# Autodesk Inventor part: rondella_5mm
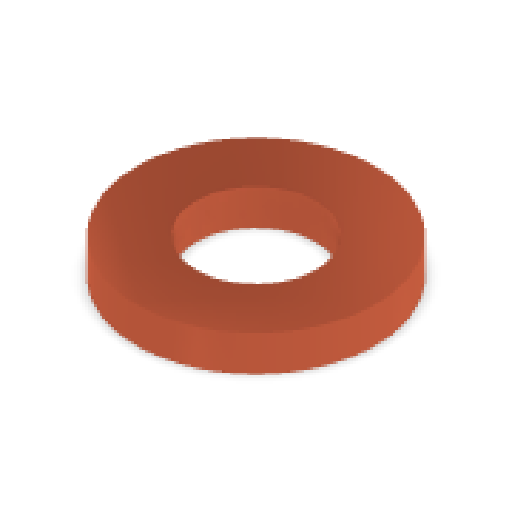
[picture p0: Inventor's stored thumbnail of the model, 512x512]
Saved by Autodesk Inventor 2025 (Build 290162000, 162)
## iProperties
Created: 2025-04
Part Number: rondella_5mm
Material: Acciaio inossidabile
Document SubType Name: Modeling
Designer: R5800u
Density: 8 g/cm^3
Appearance: Metallo 1400F caldo
Author: R5800u
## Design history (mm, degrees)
sketch "Schizzo1"
  geometry: C1 r 2.5 at (0, 0); C2 r 5 at (0, 0); 1 further point
  constraints: 2 centre point, 2 coincident
  dimensions: "d0" = 5 diameter of C1; "d1" = 10 diameter of C2
extrude "Estrusione1" new body sketch "Schizzo1" distance "d2" = 1.5; taper "d3" = 0 deg
node "Solido1"
